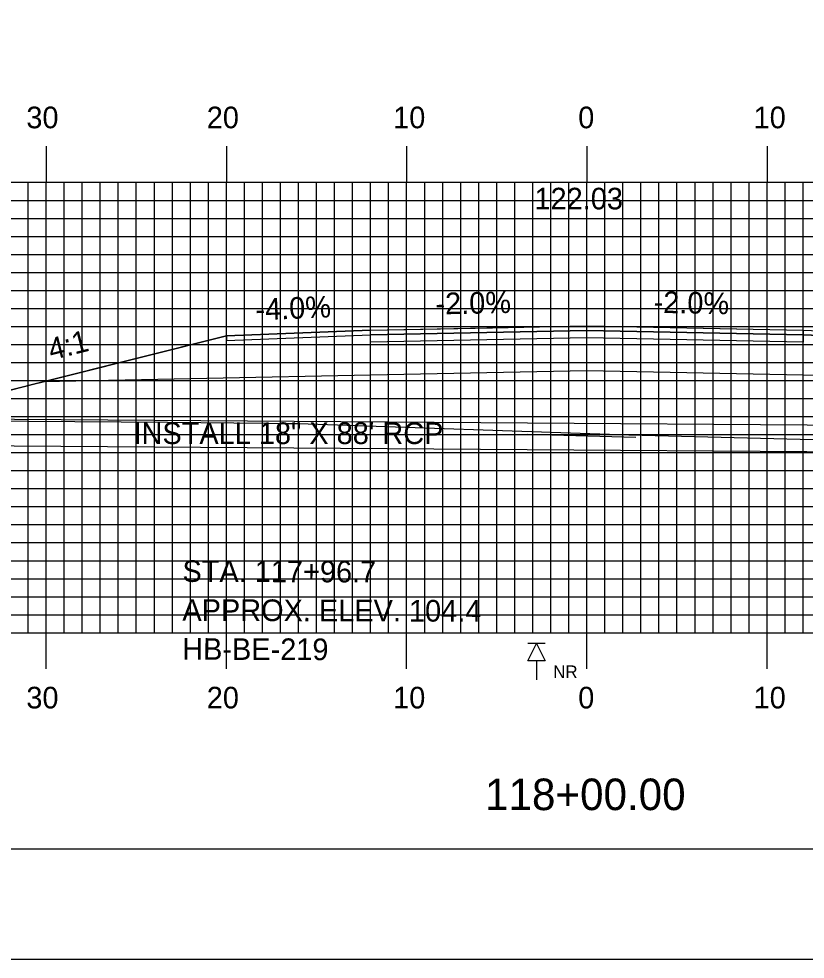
# Model space of a CAD drawing. Extents: x 1771629 to 1771972, y 442591 to 442811.
# Drawn here: x 1771763.1 to 1771806.7, y 442590.5 to 442642.7 of the extents above; entities that cross this region are included whole.
import ezdxf

# ---------------------------------------------------------------- set-up
doc = ezdxf.new("R2010")
doc.units = 0
for name, color, linetype in [('ANNOTATION', 7, 'Continuous'), ('BORDER', 7, 'Continuous'), ('BORING - NO REFUSAL', 7, 'Continuous'), ('D_Drainage_Culvert', 7, 'Continuous'), ('D_Drainage_Text', 7, 'Continuous'), ('D_Roadway_Centerline', 7, 'Continuous'), ('D_Roadway_Centerline_Text', 7, 'Continuous'), ('D_Roadway_Edge_Shoulder', 7, 'Continuous'), ('D_Roadway_Edge_TW', 7, 'Continuous'), ('D_Roadway_Pavement', 7, 'Continuous'), ('D_Roadway_SlopeLines', 7, 'Continuous'), ('D_Roadway_SubGrade', 7, 'Continuous'), ('H_V ANNOTATION', 7, 'Continuous'), ('MAJOR', 7, 'Continuous'), ('MINOR', 7, 'Continuous'), ('PLOT BOUNDARY', 7, 'Continuous'), ('S_Roadway_Centerline', 7, 'Continuous')]:
    doc.layers.add(name, color=color, linetype=linetype)

msp = doc.modelspace()

# ---------------------------------------------------------------- linework, layer by layer
at = {"layer": 'BORDER'}
msp.add_lwpolyline([(1771644.98, 442596.665), (1771964.98, 442596.665), (1771964.98, 442806.665), (1771644.98, 442806.665)], close=True, dxfattribs=at)
at = {"layer": 'BORING - NO REFUSAL'}
for p, q in [((1771792.26, 442608.065), (1771791.301, 442608.065)), ((1771791.78, 442607.106), (1771791.78, 442606.047))]:
    msp.add_line(p, q, dxfattribs=at)
msp.add_lwpolyline([(1771791.78, 442608.065), (1771792.26, 442607.106), (1771791.301, 442607.106)], close=True, dxfattribs=at)
at = {"layer": 'D_Drainage_Culvert'}
msp.add_line((1771791.299, 442619.684), (1771797.299, 442619.518), dxfattribs=at)
msp.add_lwpolyline([(1771755.035, 442620.574), (1771843.033, 442619.942), (1771843.022, 442618.442), (1771755.024, 442619.074)], close=True, dxfattribs=at)
at = {"layer": 'D_Roadway_Centerline'}
msp.add_lwpolyline([(1771759.741, 442621.427), (1771761.259, 442621.807), (1771762.581, 442622.137), (1771763.873, 442622.461), (1771764.406, 442622.594), (1771765.674, 442622.911), (1771774.58, 442625.137), (1771782.578, 442625.457), (1771782.581, 442625.457), (1771782.585, 442625.457), (1771789.339, 442625.592), (1771794.581, 442625.697), (1771794.589, 442625.697), (1771806.58, 442625.457), (1771814.581, 442625.137), (1771815.296, 442624.958), (1771824.751, 442622.595), (1771824.755, 442622.594), (1771831.544, 442620.896)], dxfattribs=at)
at = {"layer": 'D_Roadway_Edge_Shoulder'}
for points in [[(1771782.581, 442625.457), (1771774.58, 442625.137), (1771774.58, 442624.887), (1771782.581, 442625.207)], [(1771806.58, 442625.457), (1771814.581, 442625.137), (1771814.581, 442624.887), (1771806.58, 442625.207)]]:
    msp.add_lwpolyline(points, close=True, dxfattribs=at)
at = {"layer": 'D_Roadway_Edge_TW'}
msp.add_lwpolyline([(1771782.581, 442625.207), (1771782.581, 442625.457), (1771794.581, 442625.697), (1771806.58, 442625.457), (1771806.58, 442625.207), (1771794.581, 442625.447)], close=True, dxfattribs=at)
at = {"layer": 'D_Roadway_Pavement'}
msp.add_lwpolyline([(1771782.581, 442624.791), (1771782.581, 442625.207), (1771794.581, 442625.447), (1771806.58, 442625.207), (1771806.58, 442624.791), (1771794.581, 442625.031)], close=True, dxfattribs=at)
at = {"layer": 'D_Roadway_SlopeLines'}
msp.add_lwpolyline([(1771774.58, 442625.137), (1771764.406, 442622.594), (1771762.581, 442622.137), (1771759.741, 442621.427)], dxfattribs=at)
at = {"layer": 'D_Roadway_SubGrade'}
msp.add_lwpolyline([(1771782.581, 442622.957), (1771764.406, 442622.594), (1771774.58, 442625.137), (1771774.58, 442624.887), (1771782.581, 442625.207), (1771794.581, 442625.447), (1771806.58, 442625.207), (1771814.581, 442624.887), (1771814.581, 442625.137), (1771824.755, 442622.594), (1771806.58, 442622.957), (1771794.581, 442623.197)], close=True, dxfattribs=at)
at = {"layer": 'MAJOR'}
for p, q in [((1771764.58, 442635.669), (1771764.58, 442633.665)), ((1771774.58, 442635.669), (1771774.58, 442633.665)), ((1771784.58, 442635.669), (1771784.58, 442633.665)), ((1771794.58, 442635.669), (1771794.58, 442633.665)), ((1771804.58, 442635.669), (1771804.58, 442633.665)), ((1771654.58, 442633.665), (1771934.58, 442633.665)), ((1771654.58, 442633.665), (1771934.58, 442633.665)), ((1771764.58, 442608.665), (1771764.58, 442633.665)), ((1771774.58, 442608.665), (1771774.58, 442633.665)), ((1771784.58, 442608.665), (1771784.58, 442633.665)), ((1771794.58, 442608.665), (1771794.58, 442633.665)), ((1771804.58, 442608.665), (1771804.58, 442633.665)), ((1771654.58, 442628.665), (1771934.58, 442628.665)), ((1771654.58, 442623.665), (1771934.58, 442623.665)), ((1771654.58, 442618.665), (1771934.58, 442618.665)), ((1771654.58, 442613.665), (1771934.58, 442613.665)), ((1771654.58, 442608.665), (1771934.58, 442608.665)), ((1771654.58, 442608.665), (1771934.58, 442608.665)), ((1771764.58, 442606.661), (1771764.58, 442608.665)), ((1771774.58, 442606.661), (1771774.58, 442608.665)), ((1771784.58, 442606.661), (1771784.58, 442608.665)), ((1771794.58, 442606.661), (1771794.58, 442608.665)), ((1771804.58, 442606.661), (1771804.58, 442608.665))]:
    msp.add_line(p, q, dxfattribs=at)
at = {"layer": 'MINOR'}
for p, q in [((1771763.58, 442608.665), (1771763.58, 442633.665)), ((1771765.58, 442608.665), (1771765.58, 442633.665)), ((1771766.58, 442608.665), (1771766.58, 442633.665)), ((1771767.58, 442608.665), (1771767.58, 442633.665)), ((1771768.58, 442608.665), (1771768.58, 442633.665)), ((1771769.58, 442608.665), (1771769.58, 442633.665)), ((1771770.58, 442608.665), (1771770.58, 442633.665)), ((1771771.58, 442608.665), (1771771.58, 442633.665)), ((1771772.58, 442608.665), (1771772.58, 442633.665)), ((1771773.58, 442608.665), (1771773.58, 442633.665)), ((1771775.58, 442608.665), (1771775.58, 442633.665)), ((1771776.58, 442608.665), (1771776.58, 442633.665)), ((1771777.58, 442608.665), (1771777.58, 442633.665)), ((1771778.58, 442608.665), (1771778.58, 442633.665)), ((1771779.58, 442608.665), (1771779.58, 442633.665)), ((1771780.58, 442608.665), (1771780.58, 442633.665)), ((1771781.58, 442608.665), (1771781.58, 442633.665)), ((1771782.58, 442608.665), (1771782.58, 442633.665)), ((1771783.58, 442608.665), (1771783.58, 442633.665)), ((1771785.58, 442608.665), (1771785.58, 442633.665)), ((1771786.58, 442608.665), (1771786.58, 442633.665)), ((1771787.58, 442608.665), (1771787.58, 442633.665)), ((1771788.58, 442608.665), (1771788.58, 442633.665)), ((1771789.58, 442608.665), (1771789.58, 442633.665)), ((1771790.58, 442608.665), (1771790.58, 442633.665)), ((1771791.58, 442608.665), (1771791.58, 442633.665)), ((1771792.58, 442608.665), (1771792.58, 442633.665)), ((1771793.58, 442608.665), (1771793.58, 442633.665)), ((1771795.58, 442608.665), (1771795.58, 442633.665)), ((1771796.58, 442608.665), (1771796.58, 442633.665)), ((1771797.58, 442608.665), (1771797.58, 442633.665)), ((1771798.58, 442608.665), (1771798.58, 442633.665)), ((1771799.58, 442608.665), (1771799.58, 442633.665)), ((1771800.58, 442608.665), (1771800.58, 442633.665)), ((1771801.58, 442608.665), (1771801.58, 442633.665)), ((1771802.58, 442608.665), (1771802.58, 442633.665)), ((1771803.58, 442608.665), (1771803.58, 442633.665)), ((1771805.58, 442608.665), (1771805.58, 442633.665)), ((1771806.58, 442608.665), (1771806.58, 442633.665)), ((1771654.58, 442632.665), (1771934.58, 442632.665)), ((1771654.58, 442631.665), (1771934.58, 442631.665)), ((1771654.58, 442630.665), (1771934.58, 442630.665)), ((1771654.58, 442629.665), (1771934.58, 442629.665)), ((1771654.58, 442627.665), (1771934.58, 442627.665)), ((1771654.58, 442626.665), (1771934.58, 442626.665)), ((1771654.58, 442625.665), (1771934.58, 442625.665)), ((1771654.58, 442624.665), (1771934.58, 442624.665)), ((1771654.58, 442622.665), (1771934.58, 442622.665)), ((1771654.58, 442621.665), (1771934.58, 442621.665)), ((1771654.58, 442620.665), (1771934.58, 442620.665)), ((1771654.58, 442619.665), (1771934.58, 442619.665)), ((1771654.58, 442617.665), (1771934.58, 442617.665)), ((1771654.58, 442616.665), (1771934.58, 442616.665)), ((1771654.58, 442615.665), (1771934.58, 442615.665)), ((1771654.58, 442614.665), (1771934.58, 442614.665)), ((1771654.58, 442612.665), (1771934.58, 442612.665)), ((1771654.58, 442611.665), (1771934.58, 442611.665)), ((1771654.58, 442610.665), (1771934.58, 442610.665)), ((1771654.58, 442609.665), (1771934.58, 442609.665))]:
    msp.add_line(p, q, dxfattribs=at)
at = {"layer": 'PLOT BOUNDARY'}
msp.add_lwpolyline([(1771628.794, 442590.547), (1771968.794, 442590.547), (1771968.794, 442810.547), (1771628.794, 442810.547)], close=True, dxfattribs=at)
at = {"layer": 'S_Roadway_Centerline'}
msp.add_lwpolyline([(1771735.693, 442620.673), (1771741.62, 442620.724), (1771750.71, 442620.542), (1771753.896, 442620.449), (1771755.85, 442620.471), (1771771.303, 442620.344), (1771776.843, 442620.306), (1771777.606, 442620.288), (1771778.581, 442620.28), (1771796.912, 442619.652), (1771806.41, 442619.413), (1771816.58, 442619.351), (1771823.837, 442619.187), (1771834.719, 442618.832), (1771836.337, 442618.77), (1771837.241, 442618.711), (1771847.903, 442618.211), (1771857.287, 442617.889)], dxfattribs=at)

# ---------------------------------------------------------------- texts
at = {"layer": 'ANNOTATION'}
for s, rotation, p in [('-4.0%', 2.2905, (1771776.211, 442626.004)), ('-2.0%', 1.1458, (1771786.189, 442626.33)), ('-2.0%', 358.8542, (1771798.271, 442626.424)), ('4:1', 14.0335, (1771764.862, 442623.785))]:
    msp.add_text(s, height=1.2, rotation=rotation, dxfattribs=at).set_placement(p)
at = {"layer": 'BORING - NO REFUSAL'}
for s, p in [('STA. 117+96.7', (1771772.139, 442611.489)), ('APPROX. ELEV. 104.4', (1771772.132, 442609.329)), ('HB-BE-219', (1771772.125, 442607.169))]:
    msp.add_text(s, height=1.2, rotation=359.8142, dxfattribs=at).set_placement(p)
msp.add_text('NR', height=0.6998, dxfattribs=at).set_placement((1771792.713, 442606.15))
at = {"layer": 'D_Drainage_Text'}
msp.add_text('INSTALL 18" X 88\' RCP', height=1.2, dxfattribs=at).set_placement((1771769.424, 442619.138))
at = {"layer": 'D_Roadway_Centerline'}
for s, p in [('C', (1771794.575, 442625.697)), ('L', (1771794.581, 442625.69))]:
    msp.add_text(s, height=0.0146, dxfattribs=at).set_placement(p)
at = {"layer": 'D_Roadway_Centerline_Text'}
msp.add_text('122.03', height=1.2, dxfattribs=at).set_placement((1771791.673, 442632.162))
at = {"layer": 'H_V ANNOTATION'}
for s, height, p in [('30', 1.2, (1771763.478, 442636.665)), ('20', 1.2, (1771773.488, 442636.665)), ('10', 1.2, (1771783.831, 442636.665)), ('0', 1.2, (1771794.099, 442636.665)), ('10', 1.2, (1771803.831, 442636.665)), ('30', 1.2, (1771763.478, 442604.465)), ('20', 1.2, (1771773.488, 442604.465)), ('10', 1.2, (1771783.831, 442604.465)), ('0', 1.2, (1771794.099, 442604.465)), ('10', 1.2, (1771803.831, 442604.465)), ('118+00.00', 1.75, (1771788.931, 442598.821))]:
    msp.add_text(s, height=height, dxfattribs=at).set_placement(p)

doc.saveas('drawing.dxf')
